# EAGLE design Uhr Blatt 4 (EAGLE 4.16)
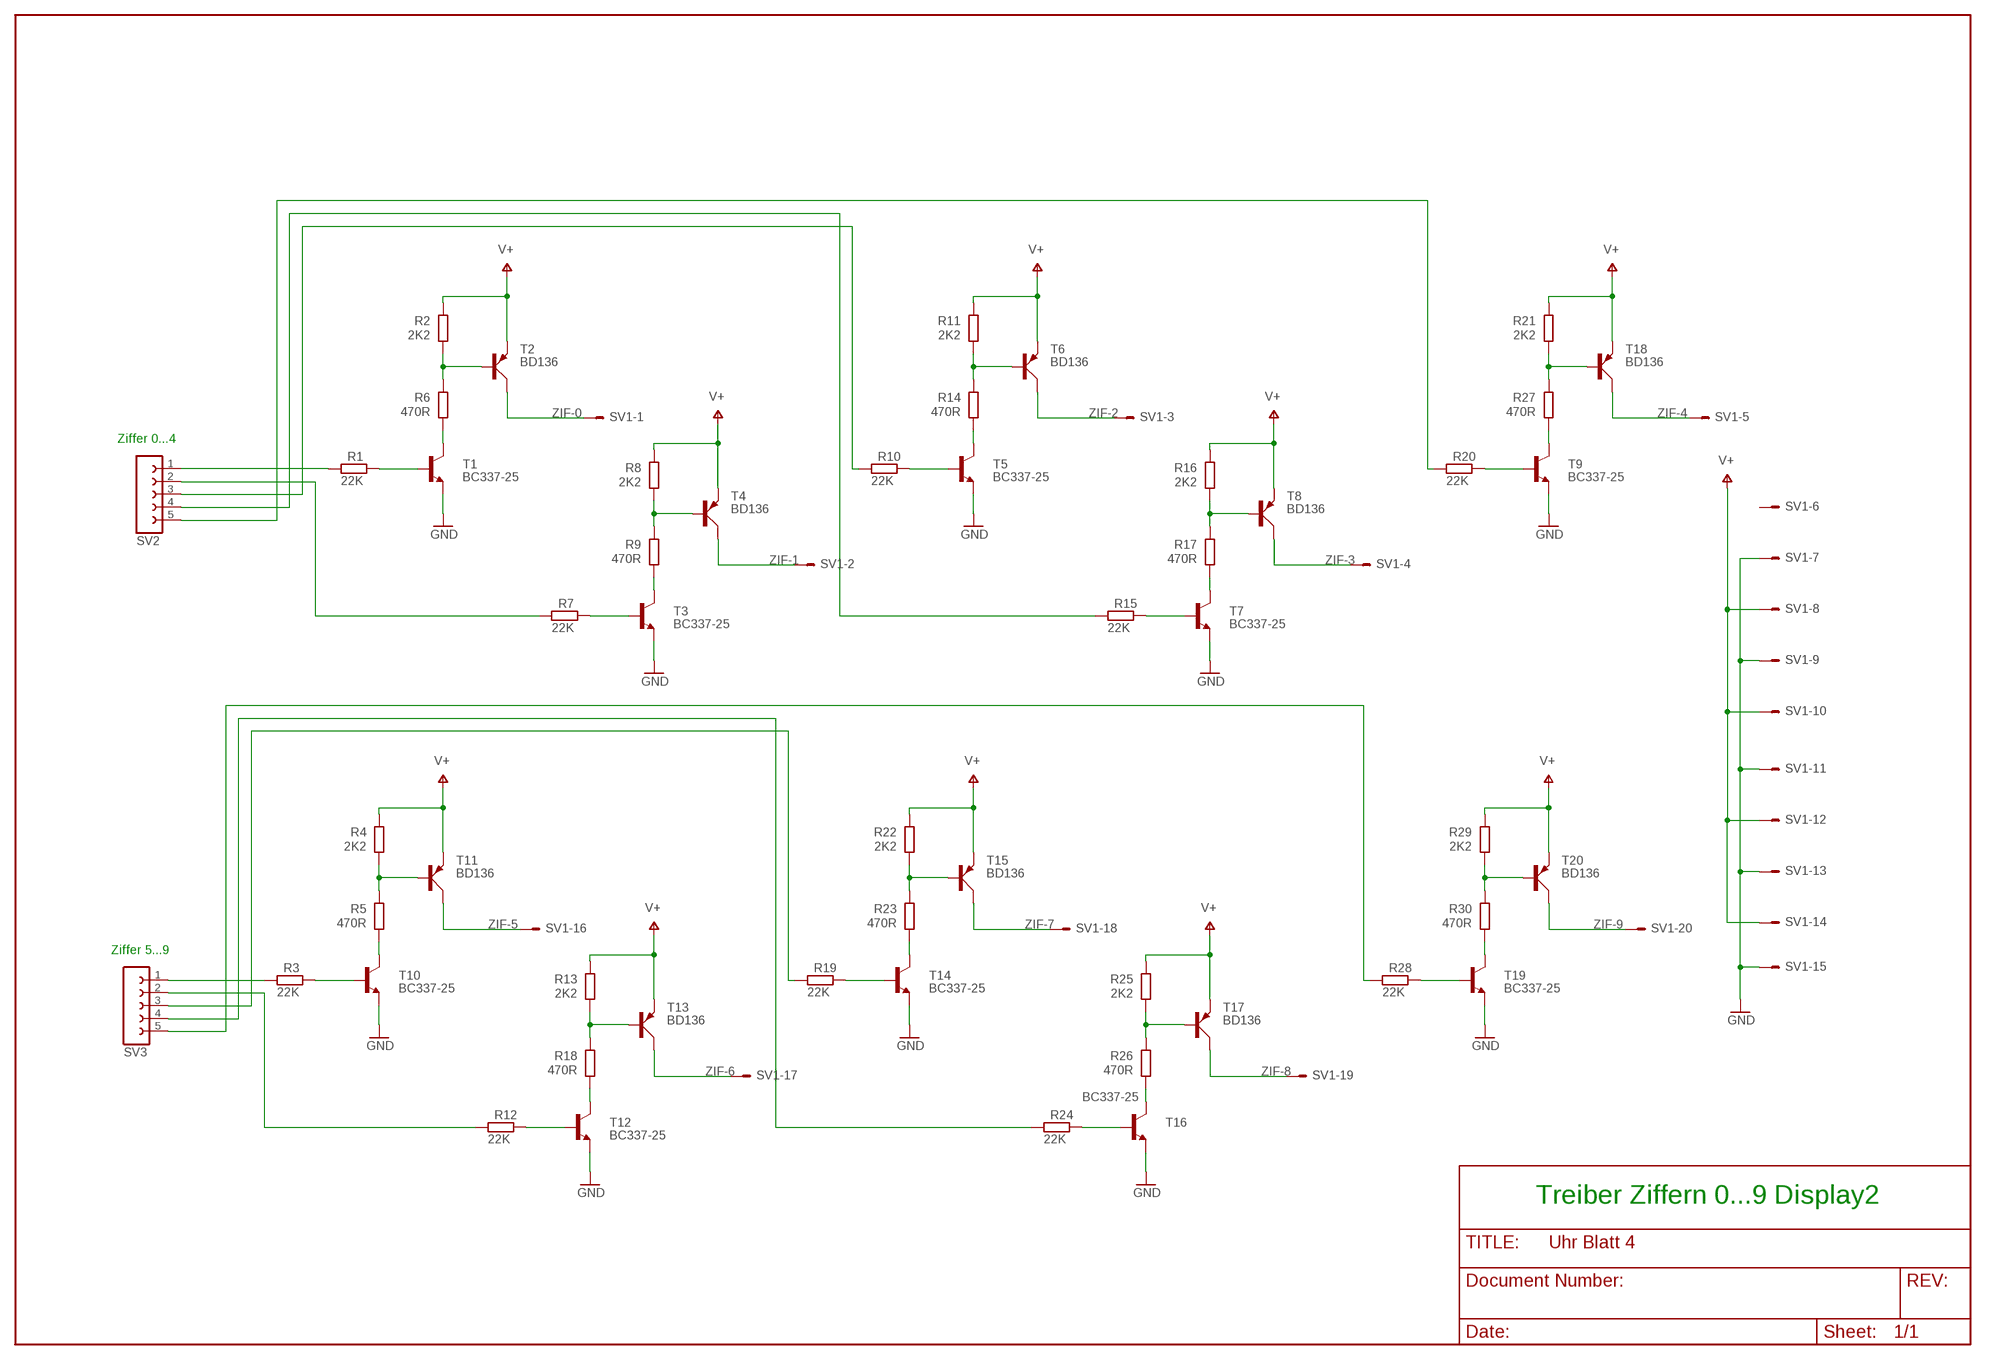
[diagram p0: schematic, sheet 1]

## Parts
R1  22K  R-EU_0207/10  [0207/10]
R2  2K2  R-EU_0207/10  [0207/10]
R3  22K  R-EU_0207/10  [0207/10]
R4  2K2  R-EU_0207/10  [0207/10]
R5  470R  R-EU_0207/10  [0207/10]
R6  470R  R-EU_0207/10  [0207/10]
R7  22K  R-EU_0207/10  [0207/10]
R8  2K2  R-EU_0207/10  [0207/10]
R9  470R  R-EU_0207/10  [0207/10]
R10  22K  R-EU_0207/10  [0207/10]
R11  2K2  R-EU_0207/10  [0207/10]
R12  22K  R-EU_0207/10  [0207/10]
R13  2K2  R-EU_0207/10  [0207/10]
R14  470R  R-EU_0207/10  [0207/10]
R15  22K  R-EU_0207/10  [0207/10]
R16  2K2  R-EU_0207/10  [0207/10]
R17  470R  R-EU_0207/10  [0207/10]
R18  470R  R-EU_0207/10  [0207/10]
R19  22K  R-EU_0207/10  [0207/10]
R20  22K  R-EU_0207/10  [0207/10]
R21  2K2  R-EU_0207/10  [0207/10]
R22  2K2  R-EU_0207/10  [0207/10]
R23  470R  R-EU_0207/10  [0207/10]
R24  22K  R-EU_0207/10  [0207/10]
R25  2K2  R-EU_0207/10  [0207/10]
R26  470R  R-EU_0207/10  [0207/10]
R27  470R  R-EU_0207/10  [0207/10]
R28  22K  R-EU_0207/10  [0207/10]
R29  2K2  R-EU_0207/10  [0207/10]
R30  470R  R-EU_0207/10  [0207/10]
SV1  ML20E  [ML20]
SV2  FE05-1  [FE05-1]
SV3  FE05-1  [FE05-1]
T1  BC337-25  [TO92]
T2  BD136  BD140  [TO126AV]
T3  BC337-25  [TO92]
T4  BD136  BD140  [TO126AV]
T5  BC337-25  [TO92]
T6  BD136  BD140  [TO126AV]
T7  BC337-25  [TO92]
T8  BD136  BD140  [TO126AV]
T9  BC337-25  [TO92]
T10  BC337-25  [TO92]
T11  BD136  BD140  [TO126AV]
T12  BC337-25  [TO92]
T13  BD136  BD140  [TO126AV]
T14  BC337-25  [TO92]
T15  BD136  BD140  [TO126AV]
T16  BC337-25  [TO92]
T17  BD136  BD140  [TO126AV]
T18  BD136  BD140  [TO126AV]
T19  BC337-25  [TO92]
T20  BD136  BD140  [TO126AV]

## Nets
GND: SV1.7 SV1.9 SV1.11 SV1.13 SV1.15 T1.1(E) T3.1(E) T5.1(E) T7.1(E) T9.1(E) T10.1(E) T12.1(E) T14.1(E) T16.1(E) T19.1(E)
N$3: R2.1 R6.2 T2.B
N$4: R1.2 T1.2(B)
N$5: R6.1 T1.3(C)
N$6: R8.1 R9.2 T4.B
N$7: R7.2 T3.2(B)
N$8: R9.1 T3.3(C)
N$9: R11.1 R14.2 T6.B
N$10: R10.2 T5.2(B)
N$11: R14.1 T5.3(C)
N$12: R16.1 R17.2 T8.B
N$13: R15.2 T7.2(B)
N$14: R17.1 T7.3(C)
N$15: R4.1 R5.2 T11.B
N$16: R21.1 R27.2 T18.B
N$17: R20.2 T9.2(B)
N$18: R27.1 T9.3(C)
N$19: R3.2 T10.2(B)
N$20: R5.1 T10.3(C)
N$21: R13.1 R18.2 T13.B
N$22: R12.2 T12.2(B)
N$23: R18.1 T12.3(C)
N$24: R22.1 R23.2 T15.B
N$25: R19.2 T14.2(B)
N$26: R23.1 T14.3(C)
N$27: R25.1 R26.2 T17.B
N$28: R24.2 T16.2(B)
N$29: R26.1 T16.3(C)
N$30: R29.1 R30.2 T20.B
N$31: R28.2 T19.2(B)
N$32: R30.1 T19.3(C)
N$33: R1.1 SV2.1
N$34: R7.1 SV2.2
N$35: R10.1 SV2.3
N$36: R15.1 SV2.4
N$37: R20.1 SV2.5
N$38: R3.1 SV3.1
N$39: R12.1 SV3.2
N$40: R19.1 SV3.3
N$41: R24.1 SV3.4
N$42: R28.1 SV3.5
V+: R2.2 R4.2 R8.2 R11.2 R13.2 R16.2 R21.2 R22.2 R25.2 R29.2 SV1.8 SV1.10 SV1.12 SV1.14 T2.E T4.E T6.E T8.E T11.E T13.E T15.E T17.E T18.E T20.E
ZIF-0: SV1.1 T2.C
ZIF-1: SV1.2 T4.C
ZIF-2: SV1.3 T6.C
ZIF-3: SV1.4 T8.C
ZIF-4: SV1.5 T18.C
ZIF-5: SV1.16 T11.C
ZIF-6: SV1.17 T13.C
ZIF-7: SV1.18 T15.C
ZIF-8: SV1.19 T17.C
ZIF-9: SV1.20 T20.C
Unconnected: SV1.6

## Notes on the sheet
- Ziffer 0...4
- Ziffer 5...9
- Treiber Ziffern 0...9 Display2

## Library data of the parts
R1-R30 = rcl:R-EU_: RESISTOR, European symbol
SV1 = con-harting-ml:ML20?E: HARTING
SV2 SV3 = con-lsta:FE05-1: FEMALE HEADER
T1 T3 T5 T7 T9 T10 T12 T14 T16 T19 = transistor-npn:BC337*: NPN Transistor
T2 T4 T6 T8 T11 T13 T15 T17 T18 T20 = transistor-power:BD140: PNP TRANSISTOR

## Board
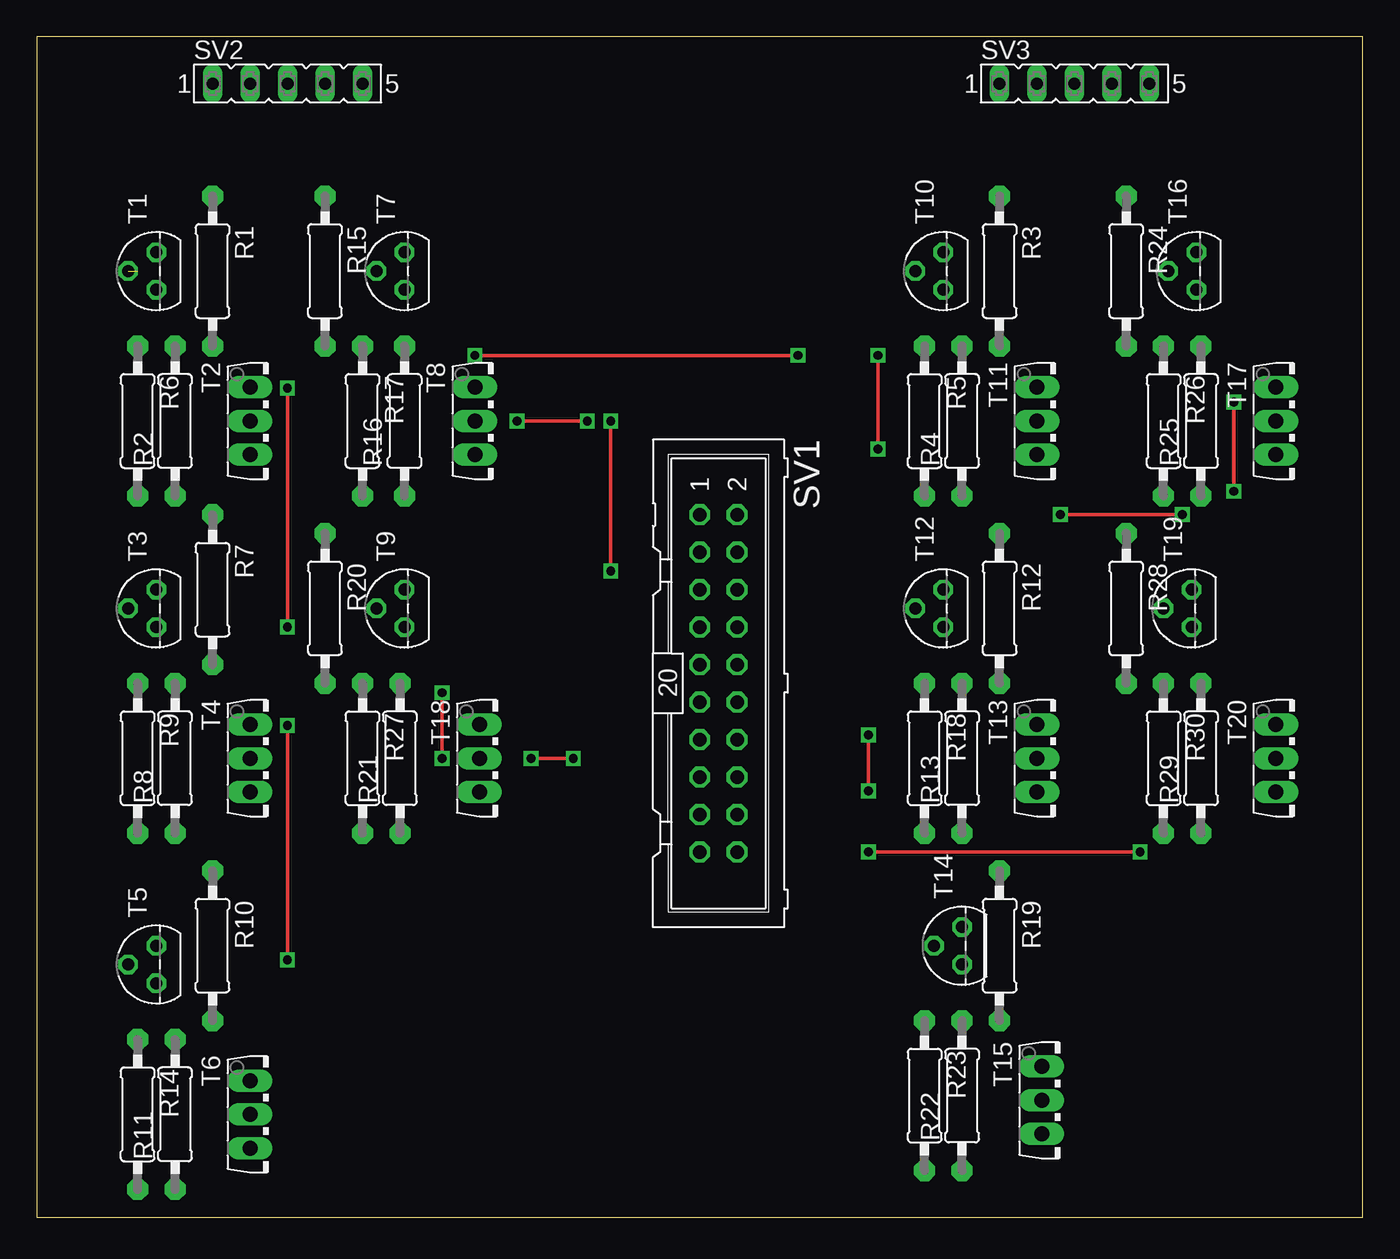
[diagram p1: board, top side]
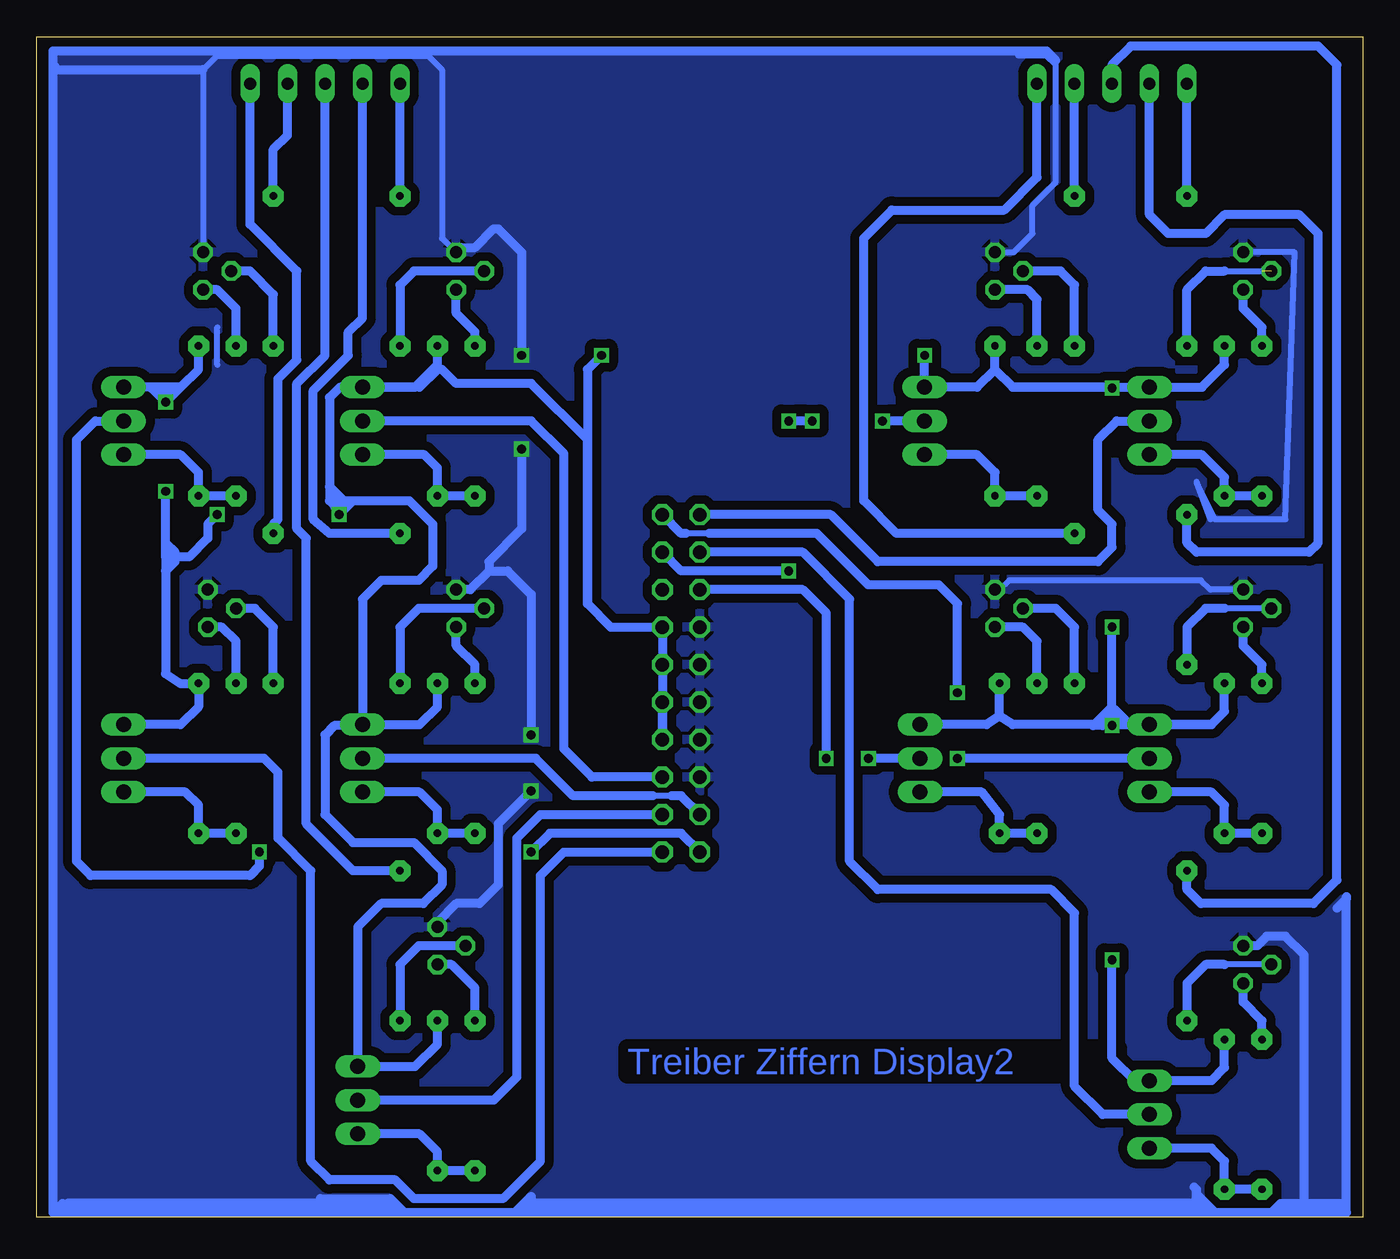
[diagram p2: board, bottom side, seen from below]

Size 89.84 x 80 mm. Coordinates in mm from the lower left corner, seen from the top.
Outline: 0,0 89.84,0 89.84,80 0,80 0,0
Copper layers (1*16): Top 0.035mm / dielectric 1.5mm / Bottom 0.035mm
Design rules "default": minimum track width 10mil, minimum drill 24mil, track to track 8mil, track to pad 8mil, pad to pad 8mil, via to via 8mil, smd to smd 8mil, copper to edge 40mil, drill to drill 8mil, minimum pad ring 10mil, minimum via ring 8mil, stop-mask expansion 4mil, vias tented up to drill 0mil, thermal gap 10mil

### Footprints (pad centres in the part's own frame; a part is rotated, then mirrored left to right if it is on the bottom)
0207/10 = drill 0.5 pad 1.422 octagon: 1 -5.08,0; 2 5.08,0
ML20 = drill 0.914 octagon: 1 -11.43,-1.27; 2 -11.43,1.27; 3 -8.89,-1.27; 4 -8.89,1.27; 5 -6.35,-1.27; 6 -6.35,1.27; 7 -3.81,-1.27; 8 -3.81,1.27; 9 -1.27,-1.27; 10 -1.27,1.27; 11 1.27,-1.27; 12 1.27,1.27; 13 3.81,-1.27; 14 3.81,1.27; 15 6.35,-1.27; 16 6.35,1.27; 17 8.89,-1.27; 18 8.89,1.27; 19 11.43,-1.27; 20 11.43,1.27
FE05-1 = drill 0.813 long: 1 -5.08,0; 2 -2.54,0; 3 0,0; 4 2.54,0; 5 5.08,0
TO92 = drill 0.813 octagon: 1 1.27,0; 2 0,1.905; 3 -1.27,0
TO126AV = drill 1.016 long: B 2.286,-1.27; C 0,-1.27; E -2.286,-1.27

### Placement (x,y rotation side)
R1  11.9,64.13 270 top
R2  9.36,53.97 90 top
R3  65.24,64.13 270 top
R4  62.7,53.97 90 top
R5  60.16,53.97 270 top
R6  6.82,53.97 270 top
R7  11.9,42.54 270 top
R8  9.36,31.11 90 top
R9  6.82,31.11 270 top
R10  11.9,18.41 270 top
R11  9.36,6.98 90 top
R12  65.24,41.27 270 top
R13  62.7,31.11 90 top
R14  6.82,6.98 270 top
R15  19.52,64.13 270 top
R16  24.92,53.97 90 top
R17  22.06,53.97 270 top
R18  60.16,31.11 270 top
R19  65.24,18.41 270 top
R20  19.52,41.27 270 top
R21  24.6,31.11 90 top
R22  62.7,8.25 90 top
R23  60.16,8.25 270 top
R24  73.81,64.13 270 top
R25  78.89,53.97 90 top
R26  76.35,53.97 270 top
R27  22.06,31.11 270 top
R28  73.81,41.27 270 top
R29  78.89,31.11 90 top
R30  76.35,31.11 270 top
SV1  46.19,36.19 270 top
SV2  16.98,76.83 0 top
SV3  70.32,76.83 0 top
T1  8.09,64.13 90 top
T2  15.71,53.97 270 top
T3  8.09,41.27 90 top
T4  15.71,31.11 270 top
T5  8.09,17.14 90 top
T6  15.71,6.98 270 top
T7  24.92,64.13 90 top
T8  30.95,53.97 270 top
T9  24.92,41.27 90 top
T10  61.43,64.13 90 top
T11  69.05,53.97 270 top
T12  61.43,41.27 90 top
T13  69.05,31.11 270 top
T14  62.7,18.41 90 top
T15  69.37,7.93 270 top
T16  78.58,64.13 90 top
T17  85.24,53.97 270 top
T18  31.27,31.11 270 top
T19  78.26,41.27 90 top
T20  85.24,31.11 270 top

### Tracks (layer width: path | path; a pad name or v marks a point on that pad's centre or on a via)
GND  (via drill 0.6)
  Top 0.254: v56.98,58.41 v56.98,52.07 | v56.35,32.7 v56.35,28.89
  Bottom 0.406: 76.67,78.73 64.29,78.73 | 77.62,57.78 77.62,60.32 | T16.1 78.58,77.78 77.62,78.73 76.67,78.73 | 76.67,78.73 63.34,78.73 62.38,77.78 62.38,66.35 T10.1 | T9.1 24.6,42.54 23.96,43.18 10.95,43.18 10.31,42.54 T3.1 | 10.31,47.3 11.27,49.84 10,47.3 5.23,47.3 4.6,65.4 T1.1 | 23.33,78.73 21.42,78.73 20.79,78.1 20.79,70.16 22.38,68.57 22.38,66.67 23.65,65.4 T7.1
  Bottom 0.61: 3.96,0.95 1.42,0.95 | 3.96,0.95 5.55,0.95 6.18,0.31 10,0.31 11.27,1.58 11.27,1.9 | T5.1 7.14,18.41 6.5,19.04 5.23,19.04 3.96,17.77 3.96,0.95 | 1.1,0.31 10.47,0.31 | 10.47,0.31 64.92,0.31 | 64.92,0.31 88.73,0.31 | 88.73,0.31 88.73,78.1 | 88.73,78.1 88.73,79.05 21.42,79.05 20.79,78.42 | 11.27,0.95 56.67,0.95 56.98,0.63 | T12.1 60.48,42.54 59.21,43.81 | 59.21,43.81 59.21,44.45 56.98,46.67 v56.98,52.07 | v56.98,58.41 56.98,65.4 58.57,66.99 58.89,66.99 60.16,65.72 61.11,65.72 T10.1 | 78.58,77.78 88.42,77.78 88.73,78.1 | T14.1 62.7,20 61.43,21.27 59.84,21.27 58.57,22.54 58.57,26.66 v56.35,28.89 | v56.35,32.7 56.35,42.22 57.94,43.81 59.21,43.81 | 88.1,0.63 70,0.63 | 88.1,0.63 88.42,0.63 | 70,0.63 69.69,0.63 | 70,0.63 70.64,1.27 65.88,1.27 65.24,0.63 69.37,0.63 | 88.1,0.63 88.1,0.95 88.73,0.31 | 87.78,0.95 65.56,0.95 64.92,0.31 | 64.92,0.31 57.46,0.31 56.35,1.42 56.35,0.79 56.51,0.63 10.95,0.63 10.95,1.11 11.27,1.42 11.27,0.95 | 11.27,0.95 11.11,0.95 10.47,0.31 | 10.47,0.31 5.71,0.31 5.39,0.63 1.42,0.63 1.1,0.31 | 1.1,0.31 1.1,21.58 | 1.1,21.58 1.1,21.74 | 1.1,21.58 1.74,20.95 | 11.27,0.95 11.27,1.9 | 11.27,1.9 11.42,2.06
  pour Bottom (isolate 0.61): 0.47,0.63 89.37,0.63 89.37,79.69 0.47,79.69
N$3
  Bottom 0.61: R6.2 R2.1 9.36,50.16 10.88,51.68 T2.B
N$4  (1 unrouted)
  Bottom 0.406: 9.36,64.13 6.82,64.13
  Bottom 0.61: R1.2 11.9,62.86 10.63,64.13 9.36,64.13
N$5
  Bottom 0.61: R6.1 6.82,60.32 8.09,61.59 T1.3
N$6
  Bottom 0.61: R9.2 R8.1 9.36,27.93 10.25,28.82 T4.B
N$7
  Bottom 0.406: T3.2 9.36,41.27
  Bottom 0.61: R7.2 11.9,40 10.63,41.27 9.36,41.27
N$8
  Bottom 0.61: R9.1 6.82,37.46 8.09,38.73 T3.3
N$9
  Bottom 0.61: R14.2 R11.1 9.36,3.8 10.25,4.69 T6.B
N$10
  Bottom 0.406: T5.2 9.36,17.14
  Bottom 0.61: R10.2 11.9,15.87 10.63,17.14 9.36,17.14
N$11
  Bottom 0.61: R14.1 6.82,13.33 8.09,14.6 T5.3
N$12
  Bottom 0.61: R17.2 R16.1 25.23,48.89 24.92,49.21 24.92,50.48 26.12,51.68 T8.B
N$13
  Bottom 0.61: T7.2 20.47,64.13 19.52,63.18 R15.2
N$14
  Bottom 0.61: R17.1 22.06,62.23 22.7,62.86 T7.3
N$15
  Bottom 0.61: R5.2 R4.1 62.7,50.8 63.59,51.68 T11.B
N$16
  Bottom 0.61: R27.2 R21.1 24.92,26.03 24.6,26.35 24.6,27.3 25.81,28.82 T18.B
N$17
  Bottom 0.61: R20.2 19.52,40 20.79,41.27 T9.2
N$18
  Bottom 0.61: R27.1 22.06,39.05 23.01,40 T9.3
N$19
  Bottom 0.61: R3.2 65.24,63.18 64.29,64.13 T10.2
N$20
  Bottom 0.61: T10.3 61.43,61.27 60.16,60 R5.1
N$21
  Bottom 0.61: R18.2 R13.1 62.7,27.62 63.91,28.82 T13.B
N$22
  Bottom 0.61: R12.2 65.24,40 63.97,41.27 T12.2
N$23
  Bottom 0.61: T12.3 61.43,38.73 60.16,37.46 R18.1
N$24
  Bottom 0.61: R23.2 R22.1 | T15.B 63.91,5.65 62.7,4.44 R22.1 | R22.1 62.7,2.85
N$25
  Bottom 0.61: R19.2 65.24,17.14 63.97,18.41 T14.2
N$26
  Bottom 0.61: T14.3 61.75,17.14 60.16,15.55 R23.1
N$27
  Bottom 0.61: R26.2 R25.1 78.89,50.48 80.1,51.68 T17.B
N$28
  Bottom 0.61: R24.2 73.81,62.54 75.4,64.13 T16.2
N$29
  Bottom 0.61: R26.1 76.35,61.59 77.62,62.86 T16.3
N$30
  Bottom 0.61: R30.2 R29.1 79.21,26.03 78.89,26.35 78.89,27.93 79.78,28.82 T20.B
N$31
  Bottom 0.61: R28.2 73.81,40 75.08,41.27 T19.2
N$32
  Bottom 0.61: R30.1 76.35,39.05 77.3,40 T19.3
N$33
  Bottom 0.61: R1.1 SV2.1
N$34
  Bottom 0.61: SV2.2 14.44,67.94 13.17,66.67 10.63,66.67 9.36,67.94 4.28,67.94 3.01,66.67 3.01,45.72 3.64,45.08 11.27,45.08 11.9,45.72 R7.1
N$35
  Bottom 0.61: SV2.3 16.98,78.1 15.71,79.37 3.01,79.37 1.74,78.1 1.74,22.86 3.33,21.27 10.95,21.27 11.9,22.22 R10.1
N$36
  Bottom 0.61: R15.1 SV2.4
N$37
  Bottom 0.61: R20.1 31.58,46.35 33.81,48.57 33.81,66.35 31.9,68.26 24.28,68.26 22.06,70.48 SV2.5
N$38
  Bottom 0.61: R3.1 SV3.1
N$39
  Bottom 0.61: SV3.2 67.78,60.96 68.73,60 68.73,58.41 71.11,56.03 71.11,47.3 70,46.35 R12.1
N$40
  Bottom 0.61: R19.1 68.41,23.49 71.59,26.66 71.59,46.03 72.22,46.67 72.22,56.51 70.32,58.41 SV3.3
N$41
  Bottom 0.61: SV3.4 72.86,73.34 73.81,72.38 R24.1
N$42
  Bottom 0.61: SV3.5 75.4,67.3 72.22,64.13 72.22,58.1 73.5,56.83 73.5,47.3 73.81,46.98 R28.1
V+  (via drill 0.6)
  Top 0.254: v16.98,40 v16.98,56.19 | v16.98,17.46 v16.98,33.33 | v69.37,47.62 v77.62,47.62 | v81.11,49.21 v81.11,55.24 | v29.68,58.41 v51.59,58.41
  Bottom 0.61: R2.2 9.36,57.78 10.88,56.26 T2.E 23.71,56.26 | 10.25,33.4 T4.E 16.03,33.4 | 10.25,33.4 9.36,34.29 R8.2 | R11.2 9.36,10.16 10.25,9.27 T6.E 14.44,9.2 15.39,9.2 16.98,10.79 v16.98,17.46 | 23.71,56.26 24.92,57.46 | 24.92,57.46 R16.2 | T8.E 26.12,56.26 24.92,57.46 | 16.03,33.4 23.71,33.4 24.6,33.97 | 24.6,33.97 R21.2 | T18.E 25.49,33.4 24.6,33.97 | 23.71,56.26 17.04,56.26 v16.98,56.19 | 16.03,33.4 16.03,33.65 16.66,34.29 | 16.98,34.6 v16.98,40 | 16.66,34.29 16.98,34.6 | 10.25,33.4 16.98,33.4 v16.98,33.33 | 16.98,34.6 18.25,33.33 17.61,33.33 16.66,34.29 | SV1.8 SV1.10 SV1.12 SV1.14 SV1.8 | T11.E 64.22,56.26 62.7,57.78 R4.2 | T11.E 63.91,56.26 62.7,57.46 62.38,57.46 61.43,56.51 56.35,56.51 52.54,52.7 52.54,41.59 | T11.E 69.3,56.26 70,55.56 | 70,55.56 70,49.53 69.05,48.57 68.41,48.57 | 68.41,48.57 64.61,48.57 63.02,46.98 63.02,44.13 63.97,43.18 66.51,43.18 67.78,41.91 67.78,33.33 | R13.2 62.7,34.6 63.91,33.4 T13.E 68.03,33.4 67.78,33.33 | T15.E 64.22,10.22 62.7,11.74 R22.2 | 67.78,33.33 69.69,33.33 70.32,32.7 70.32,27.3 68.41,25.39 64.29,25.39 62.38,23.49 62.38,22.54 63.65,21.27 66.51,21.27 68.1,19.68 T15.E | T15.E 68.1,10.16 | T20.E 80.1,33.4 78.89,34.6 R29.2 80.16,36.19 81.11,36.83 81.11,43.81 | 80.1,56.26 T17.E | 80.1,56.26 78.89,57.46 R25.2 | 70,55.56 70,48.57 69.37,47.94 v69.37,47.62 | v69.37,47.62 69.37,48.57 69.69,48.89 69.69,48.26 v69.37,47.62 | v77.62,47.62 78.26,46.98 78.26,46.03 79.53,44.76 80.48,44.76 | 80.48,44.76 81.11,44.76 | 81.11,44.76 81.11,43.81 | 68.41,48.57 v69.37,47.62 | v81.11,55.24 80.1,56.26 | v81.11,55.24 82.07,56.19 81.43,56.19 81.11,55.88 v81.11,55.24 | 81.11,44.76 81.11,45.4
  Bottom 0.61: 81.11,45.4 81.11,45.72 | 81.11,45.72 v81.11,49.21 | 80.48,44.76 81.11,45.4 | 81.11,43.81 80.48,44.45 | 81.11,45.72 80.48,45.08 | SV1.8 50.95,40 52.54,41.59 | 52.54,41.59 52.54,57.46 v51.59,58.41 | T8.E 29.68,56.19 | T8.E v29.68,58.41
ZIF-0
  Bottom 0.61: T2.C 16.66,53.97 17.93,52.7 17.93,47.94 16.98,46.98 16.98,45.4 17.93,44.45 32.85,44.45 36.03,47.62 44.6,47.62 44.92,47.3 SV1.1
ZIF-1  (via drill 0.6)
  Top 0.254: v27.46,31.11 v27.46,35.55
  Bottom 0.406: 44.28,46.35 45.87,46.35
  Bottom 0.61: v27.46,35.55 27.46,41.59 28.73,42.86 33.49,42.86 36.98,46.35 44.28,46.35 | T4.C v27.46,31.11 | 45.87,46.35 46.19,46.35 SV1.2
ZIF-2
  Bottom 0.61: SV1.3 37.94,45.08 34.76,41.91 34.76,24.12 32.85,22.22 21.11,22.22 19.52,20.63 19.52,8.89 17.61,6.98 T6.C
ZIF-3  (via drill 0.6)
  Top 0.254: v38.89,53.97 v38.89,43.81 | v32.54,53.97 v37.3,53.97
  Bottom 0.61: SV1.4 46.19,43.81 v38.89,43.81 | v37.3,53.97 v38.89,53.97 | T8.C v32.54,53.97
ZIF-4  (via drill 0.6)
  Top 0.254: v33.49,31.11 v36.35,31.11
  Bottom 0.61: SV1.5 37.94,42.54 36.35,40.95 v36.35,31.11 | T18.C v33.49,31.11
ZIF-5
  Bottom 0.61: T11.C 56.35,53.97 54.13,51.75 54.13,31.74 52.22,29.84 SV1.16
ZIF-6
  Bottom 0.406: 46.82,28.57 48.09,28.57
  Bottom 0.61: SV1.17 46.19,28.57 46.82,28.57 | 48.09,28.57 53.49,28.57 56.03,31.11 T13.C 68.1,31.11
ZIF-7
  Bottom 0.61: T15.C 58.89,7.93 57.3,9.52 57.3,25.71 55.71,27.3 SV1.18
ZIF-8  (via drill 0.6)
  Top 0.254: v56.35,24.76 v74.77,24.76
  Bottom 0.61: SV1.19 46.19,26.03 55.08,26.03 v56.35,24.76 | v74.77,24.76 74.77,23.81 75.4,23.17 86.19,23.17 87.15,24.12 87.15,52.7 85.88,53.97 T17.C
ZIF-9
  Bottom 0.61: SV1.20 54.13,24.76 55.71,23.17 55.71,3.8 58.25,1.27 64.29,1.27 65.56,2.54 70,2.54 71.27,3.8 71.27,23.49 73.5,25.71 73.5,30.16 74.45,31.11 83.66,31.11 83.97,30.79 T20.C

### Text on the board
Bottom: Treiber Ziffern Display2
